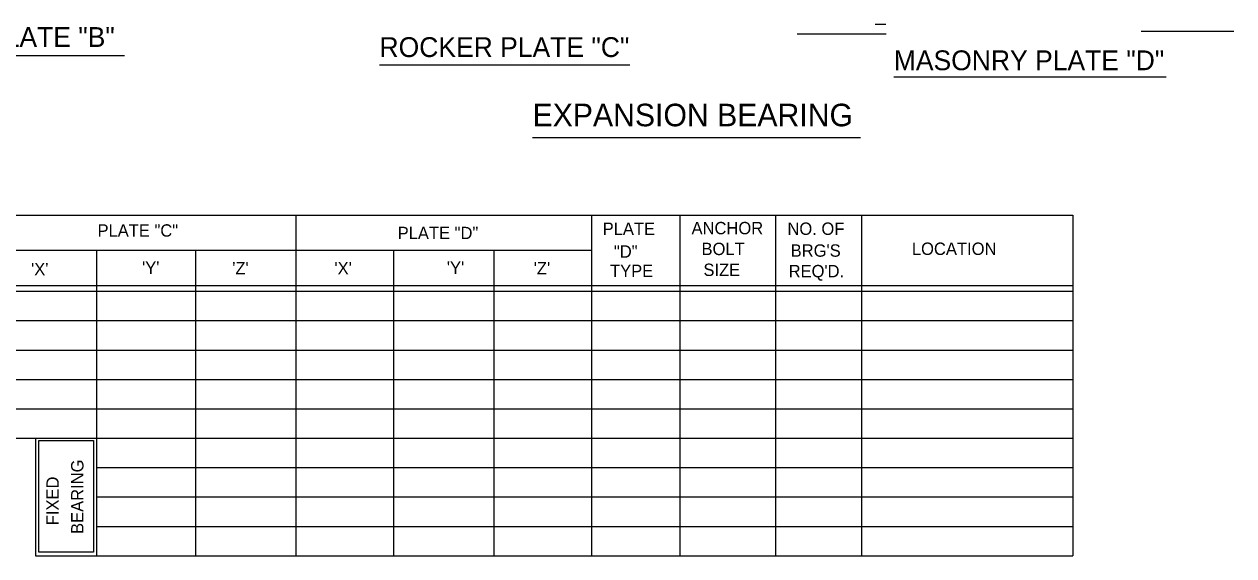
# Model space of a CAD drawing. Extents: x -1.11 to 2, y -1.43 to 1.11.
# Drawn here: x -0.387 to 0.631, y -0.041 to 0.407 of the extents above; entities that cross this region are included whole.
import ezdxf

# ---------------------------------------------------------------- set-up
doc = ezdxf.new("R2010")
doc.units = 0
doc.layers.add('Level 2', color=7, linetype='Continuous')

msp = doc.modelspace()

# ---------------------------------------------------------------- linework, layer by layer
at = {"layer": 'Level 2'}
for p, q in [((0.3382, 0.3982), (0.2632, 0.3982)), ((0.3288, 0.4067), (0.3379, 0.4067)), ((0.6307, 0.4005), (0.5529, 0.4005)), ((-0.4581, 0.3805), (-0.3027, 0.3805)), ((-0.0882, 0.3726), (0.1225, 0.3726)), ((0.3446, 0.3625), (0.5737, 0.3625)), ((0.0406, 0.3115), (0.3166, 0.3115)), ((-0.7998, 0.246), (0.4953, 0.246)), ((-0.1587, 0.246), (-0.1587, -0.0407)), ((0.0903, 0.246), (0.0903, -0.0407)), ((0.1646, 0.246), (0.1646, -0.0407)), ((0.2451, 0.246), (0.2451, -0.0407)), ((0.3173, 0.246), (0.3173, -0.0407)), ((0.4953, 0.246), (0.4953, -0.0407)), ((-0.7468, 0.2164), (0.0903, 0.2164)), ((-0.3263, 0.2164), (-0.3263, -0.0407)), ((-0.2431, 0.2164), (-0.2431, -0.0407)), ((-0.0764, 0.2164), (-0.0764, -0.0407)), ((0.008, 0.2164), (0.008, -0.0407)), ((-0.7998, 0.1869), (0.4953, 0.1869)), ((-0.7468, 0.182), (0.4953, 0.182)), ((-0.7468, 0.1573), (0.4953, 0.1573)), ((-0.7468, 0.1325), (0.4953, 0.1325)), ((-0.7468, 0.1078), (0.4953, 0.1078)), ((-0.7468, 0.083), (0.4953, 0.083)), ((-0.7998, 0.0583), (0.4953, 0.0583)), ((-0.3776, 0.0583), (-0.3776, -0.0407)), ((-0.3263, 0.0335), (0.4953, 0.0335)), ((-0.3263, 0.0088), (0.4953, 0.0088)), ((-0.3263, -0.016), (0.4953, -0.016)), ((-0.3776, -0.0407), (0.4953, -0.0407))]:
    msp.add_line(p, q, dxfattribs=at)
msp.add_lwpolyline([(-0.3289, -0.0378), (-0.3748, -0.0378), (-0.3748, 0.0562), (-0.3289, 0.0562)], close=True, dxfattribs=at)

# ---------------------------------------------------------------- texts
for s, height, p in [('ON PLATE "B"', 0.016667, (-0.4581, 0.3876)), ('ROCKER PLATE "C"', 0.016667, (-0.0882, 0.3791)), ('MASONRY PLATE "D"', 0.016667, (0.3446, 0.368)), ('EXPANSION BEARING', 0.019, (0.0406, 0.3208)), ('PLATE "C"', 0.0104, (-0.3255, 0.2279)), ('PLATE "D"', 0.0104, (-0.0729, 0.2258)), ('PLATE', 0.0104, (0.0996, 0.2294)), ('ANCHOR', 0.0104, (0.1744, 0.2299)), ('NO. OF', 0.0104, (0.2551, 0.2294)), (' "D"', 0.0104, (0.1052, 0.2102)), ('BOLT', 0.0104, (0.1828, 0.2124)), ("BRG'S", 0.01042, (0.2578, 0.211)), ('LOCATION', 0.01042, (0.3598, 0.2125)), ("'X'", 0.0104, (-0.3814, 0.1954)), ("'Y'", 0.0104, (-0.288, 0.1966)), ("'Z'", 0.0104, (-0.2121, 0.1962)), ("'X'", 0.0104, (-0.1261, 0.1962)), ("'Y'", 0.0104, (-0.0315, 0.1966)), ("'Z'", 0.0104, (0.0416, 0.1962)), ('TYPE', 0.0104, (0.1058, 0.1939)), ('SIZE', 0.0104, (0.1844, 0.1948)), ("REQ'D.", 0.0104, (0.2561, 0.1937))]:
    msp.add_text(s, height=height, dxfattribs=at).set_placement(p)
for s, p in [('BEARING', (-0.3373, -0.0223)), ('FIXED', (-0.3581, -0.015))]:
    msp.add_text(s, height=0.0104, rotation=90, dxfattribs=at).set_placement(p)

doc.saveas('drawing.dxf')
